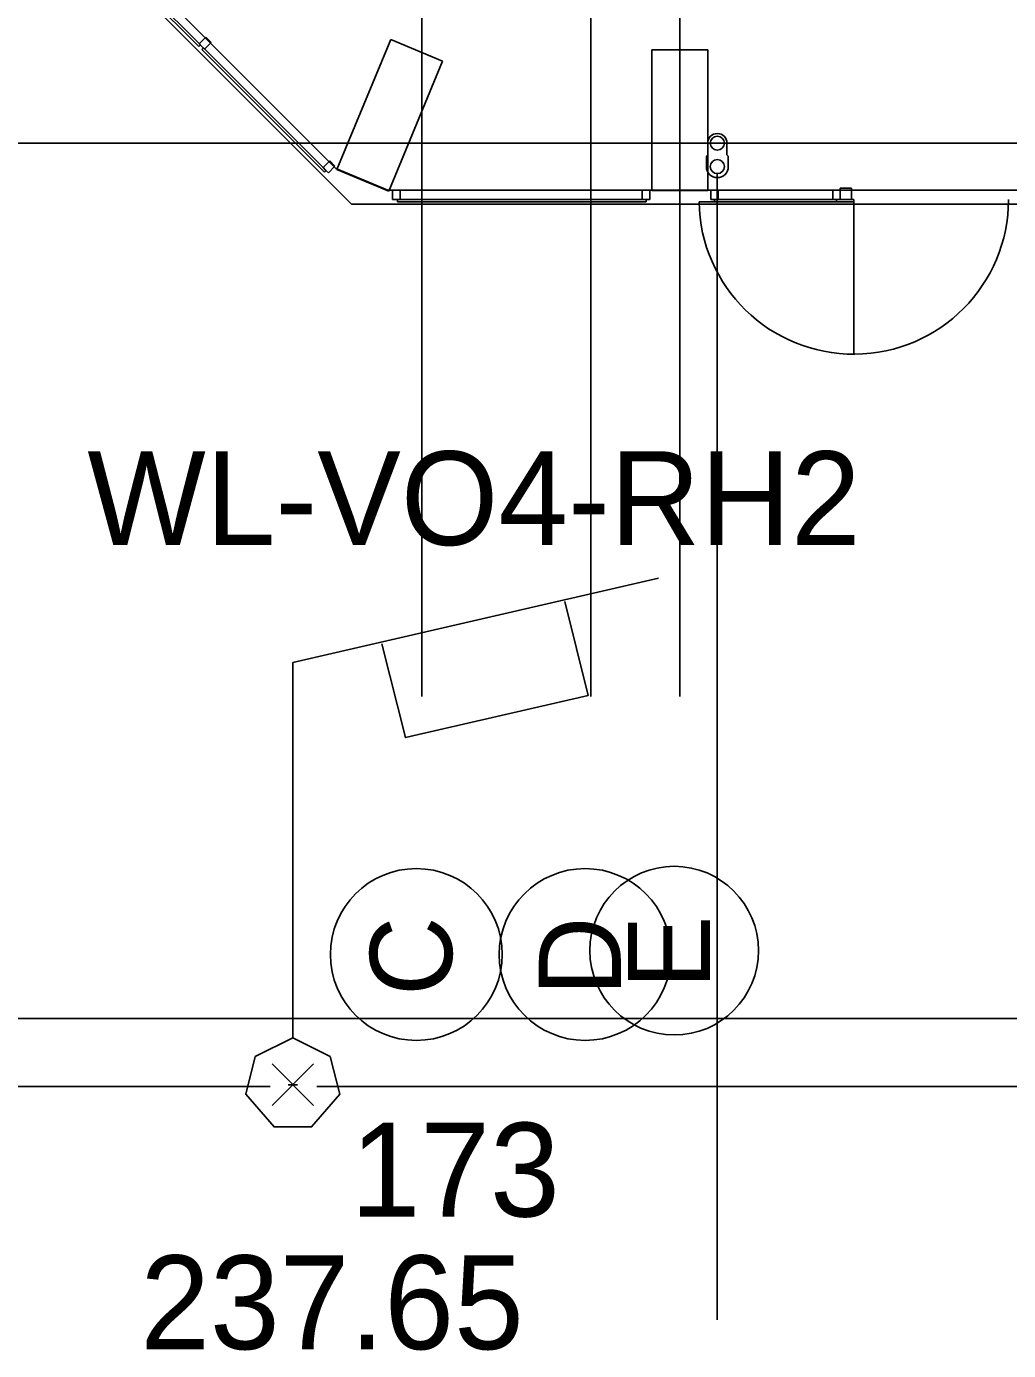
# Model space of a CAD drawing. Extents: x -264222 to -263592, y -1242345 to -1242048.
# Drawn here: x -263898.44 to -263887.96, y -1242253.68 to -1242239.56 of the extents above; entities that cross this region are included whole.
import ezdxf

# ---------------------------------------------------------------- set-up
doc = ezdxf.new("R2010")
doc.units = 0
for name, color, linetype in [('BOD_CISLO', 7, 'Continuous'), ('BOD_SYMBOL', 7, 'Continuous'), ('BOD_VYSKA', 7, 'Continuous'), ('HESCON_OSI_STAVBY_KFA', 7, 'Continuous'), ('KFA_2D_SITUACIA_DSP', 7, 'Continuous'), ('KFA_SO_62-1_VO_LAMPY_MERANE', 7, 'Continuous'), ('KFA_SO_62-1_VO_POPIS_LAMP_PROJEKT', 7, 'Continuous'), ('KFA_SO_62-1_VO_TRASA_KABLOV_PROJEKT', 7, 'Continuous')]:
    doc.layers.add(name, color=color, linetype=linetype)

msp = doc.modelspace()

# ---------------------------------------------------------------- linework, layer by layer
at = {"layer": 'BOD_SYMBOL'}
for p, q in [((-263895.816, -1242251.066), (-263895.374, -1242250.624)), ((-263895.374, -1242251.066), (-263895.816, -1242250.624))]:
    msp.add_line(p, q, dxfattribs=at)
at = {"layer": 'HESCON_OSI_STAVBY_KFA'}
for p, q in [((-263894.218, -1242083.237), (-263894.218, -1242246.707)), ((-263892.418, -1242083.237), (-263892.418, -1242246.707)), ((-263891.468, -1242083.237), (-263891.468, -1242246.707)), ((-263792.653, -1242240.807), (-263911.523, -1242240.807))]:
    msp.add_line(p, q, dxfattribs=at)
for centre, radius in [((-263894.278, -1242249.457), 0.916), ((-263892.478, -1242249.457), 0.916), ((-263891.528, -1242249.416), 0.899)]:
    msp.add_circle(centre, radius, dxfattribs=at)
at = {"layer": 'KFA_2D_SITUACIA_DSP'}
for p, q in [((-263908.663, -1242227.55), (-263895.135, -1242241.078)), ((-263897.906, -1242238.469), (-263896.598, -1242239.778)), ((-263896.58, -1242239.76), (-263897.888, -1242238.452)), ((-263896.522, -1242239.677), (-263896.592, -1242239.748)), ((-263896.465, -1242239.733), (-263896.522, -1242239.677)), ((-263896.598, -1242239.778), (-263896.58, -1242239.76)), ((-263896.592, -1242239.748), (-263896.564, -1242239.776)), ((-263896.566, -1242239.809), (-263896.548, -1242239.792)), ((-263895.258, -1242241.118), (-263896.566, -1242239.809)), ((-263896.564, -1242239.776), (-263896.536, -1242239.804)), ((-263896.548, -1242239.792), (-263895.24, -1242241.1)), ((-263896.536, -1242239.804), (-263896.465, -1242239.733)), ((-263894.551, -1242239.702), (-263895.125, -1242241.088)), ((-263893.997, -1242239.932), (-263894.551, -1242239.702)), ((-263891.768, -1242241.312), (-263891.768, -1242239.812)), ((-263891.768, -1242239.812), (-263891.168, -1242239.812)), ((-263891.168, -1242239.812), (-263891.168, -1242241.312)), ((-263894.571, -1242241.318), (-263893.997, -1242239.932)), ((-263891.171, -1242240.807), (-263891.171, -1242240.932)), ((-263890.965, -1242240.807), (-263890.965, -1242240.932)), ((-263891.171, -1242240.932), (-263891.185, -1242240.946)), ((-263891.185, -1242240.946), (-263891.185, -1242241.057)), ((-263890.965, -1242240.932), (-263890.951, -1242240.946)), ((-263890.951, -1242241.057), (-263890.951, -1242240.946)), ((-263890.951, -1242240.946), (-263890.951, -1242241.057)), ((-263895.202, -1242240.996), (-263895.273, -1242241.067)), ((-263895.273, -1242241.067), (-263895.245, -1242241.095)), ((-263895.245, -1242241.095), (-263895.216, -1242241.123)), ((-263895.216, -1242241.123), (-263895.146, -1242241.053)), ((-263895.146, -1242241.053), (-263895.202, -1242240.996)), ((-263895.135, -1242241.078), (-263894.581, -1242241.307)), ((-263895.125, -1242241.088), (-263894.571, -1242241.318)), ((-263895.24, -1242241.1), (-263895.258, -1242241.118)), ((-263891.068, -1242241.132), (-263891.068, -1242253.353)), ((-263894.581, -1242241.307), (-263809.355, -1242241.307)), ((-263894.531, -1242241.407), (-263894.531, -1242241.307)), ((-263894.531, -1242241.307), (-263894.451, -1242241.307)), ((-263894.451, -1242241.307), (-263894.451, -1242241.407)), ((-263891.868, -1242241.407), (-263891.868, -1242241.307)), ((-263891.868, -1242241.307), (-263891.788, -1242241.307)), ((-263891.788, -1242241.307), (-263891.788, -1242241.407)), ((-263891.168, -1242241.312), (-263891.768, -1242241.312)), ((-263891.058, -1242241.307), (-263891.138, -1242241.307)), ((-263891.138, -1242241.307), (-263891.138, -1242241.407)), ((-263891.058, -1242241.407), (-263891.058, -1242241.307)), ((-263889.838, -1242241.407), (-263889.838, -1242241.307)), ((-263889.838, -1242241.307), (-263889.758, -1242241.307)), ((-263889.638, -1242241.287), (-263889.758, -1242241.287)), ((-263889.758, -1242241.287), (-263889.758, -1242241.407)), ((-263889.758, -1242241.307), (-263889.758, -1242241.407)), ((-263889.638, -1242241.407), (-263889.638, -1242241.287)), ((-263894.491, -1242241.407), (-263894.531, -1242241.407)), ((-263894.451, -1242241.407), (-263894.491, -1242241.407)), ((-263891.828, -1242241.407), (-263894.478, -1242241.407)), ((-263894.478, -1242241.407), (-263894.478, -1242241.432)), ((-263894.478, -1242241.432), (-263891.828, -1242241.432)), ((-263891.828, -1242241.407), (-263891.868, -1242241.407)), ((-263891.828, -1242241.432), (-263891.828, -1242241.407)), ((-263891.788, -1242241.407), (-263891.828, -1242241.407)), ((-263891.263, -1242241.432), (-263889.613, -1242241.432)), ((-263891.138, -1242241.407), (-263891.098, -1242241.407)), ((-263891.098, -1242241.432), (-263891.098, -1242241.407)), ((-263891.098, -1242241.407), (-263889.798, -1242241.407)), ((-263891.098, -1242241.407), (-263891.058, -1242241.407)), ((-263889.798, -1242241.432), (-263891.098, -1242241.432)), ((-263889.798, -1242241.407), (-263889.838, -1242241.407)), ((-263889.798, -1242241.407), (-263889.798, -1242241.432)), ((-263889.758, -1242241.407), (-263889.798, -1242241.407)), ((-263889.758, -1242241.407), (-263889.638, -1242241.407)), ((-263889.638, -1242241.407), (-263889.613, -1242241.407)), ((-263889.613, -1242241.407), (-263889.613, -1242243.057)), ((-263924.143, -1242250.14), (-263788.143, -1242250.14))]:
    msp.add_line(p, q, dxfattribs=at)
msp.add_lwpolyline([(-263794.893, -1242227.382), (-263808.968, -1242241.457), (-263894.968, -1242241.457), (-263909.043, -1242227.382), (-263909.043, -1242196.333), (-263914.143, -1242196.333), (-263914.143, -1242132.433), (-263909.043, -1242132.433), (-263909.043, -1242101.382), (-263894.968, -1242087.307), (-263808.968, -1242087.307), (-263794.893, -1242101.382), (-263794.893, -1242227.382)], dxfattribs=at)
for centre in [(-263891.068, -1242240.807), (-263891.068, -1242241.057)]:
    msp.add_circle(centre, 0.075, dxfattribs=at)
for centre, radius, start, end in [((-263891.068, -1242240.807), 0.103, 360, 180), ((-263891.068, -1242241.057), 0.117, 180, 360), ((-263889.613, -1242241.407), 1.65, 180.8682, 0)]:
    msp.add_arc(centre, radius, start, end, dxfattribs=at)
at = {"layer": 'KFA_SO_62-1_VO_LAMPY_MERANE'}
for p, q in [((-263895.645, -1242250.845), (-263895.545, -1242250.845)), ((-263895.595, -1242250.845), (-263895.595, -1242250.845))]:
    msp.add_line(p, q, dxfattribs=at)
for points in [[(-263895.595, -1242250.345), (-263895.995, -1242250.545), (-263896.095, -1242250.945), (-263895.795, -1242251.295), (-263895.395, -1242251.295), (-263895.095, -1242250.945), (-263895.195, -1242250.545), (-263895.595, -1242250.345), (-263895.595, -1242246.345), (-263891.695, -1242245.445)], [(-263892.695, -1242245.695), (-263892.445, -1242246.695), (-263894.395, -1242247.145), (-263894.645, -1242246.145)]]:
    msp.add_lwpolyline(points, dxfattribs=at)
at = {"layer": 'KFA_SO_62-1_VO_TRASA_KABLOV_PROJEKT'}
for p, q in [((-263895.838, -1242250.863), (-263914.838, -1242250.863)), ((-263876.338, -1242250.863), (-263895.338, -1242250.863))]:
    msp.add_line(p, q, dxfattribs=at)

# ---------------------------------------------------------------- texts
at = {"layer": 'BOD_CISLO'}
msp.add_text('173', height=1, dxfattribs=at).set_placement((-263894.979, -1242252.251))
at = {"layer": 'BOD_VYSKA'}
msp.add_text('237.65', height=1, dxfattribs=at).set_placement((-263897.222, -1242253.665))
at = {"layer": 'HESCON_OSI_STAVBY_KFA'}
for s, p in [('C', (-263893.897, -1242249.898)), ('D', (-263892.097, -1242249.898)), ('E', (-263891.147, -1242249.824))]:
    msp.add_text(s, height=0.875, rotation=90, dxfattribs=at).set_placement(p)
at = {"layer": 'KFA_SO_62-1_VO_POPIS_LAMP_PROJEKT'}
msp.add_text('WL-VO4-RH2', height=1, dxfattribs=at).set_placement((-263897.786, -1242245.092))

doc.saveas('drawing.dxf')
